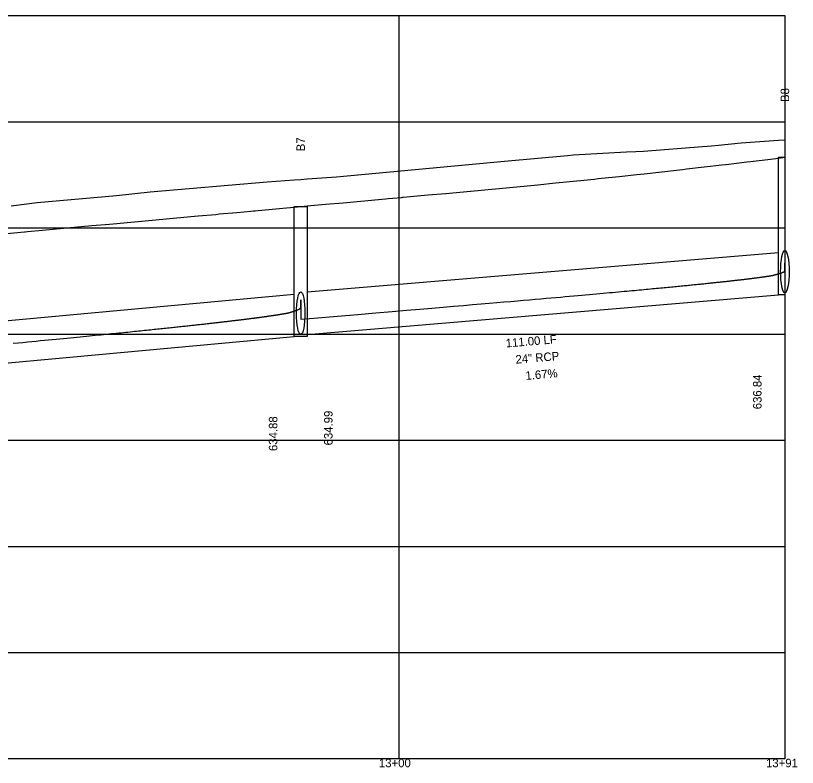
# Model space of a CAD drawing. Extents: x 2254979 to 2278074, y 13790855 to 13792793.
# Drawn here: x 2261170.4 to 2261354.4, y 13792139.4 to 13792316.4 of the extents above; entities that cross this region are included whole.
import ezdxf

# ---------------------------------------------------------------- set-up
doc = ezdxf.new("R2010")
doc.units = 0
for name, color, linetype in [('blank4', 7, 'Continuous'), ('D_DRN_PROF_HGL', 7, 'Continuous'), ('D_PROF_1', 7, 'Continuous'), ('D_PROF_NOTES_1', 7, 'Continuous'), ('Default', 7, 'Continuous'), ('Drain_PipeInside', 7, 'Continuous'), ('E_Terrain', 7, 'Continuous'), ('Inlet', 7, 'Continuous'), ('z - Construction', 7, 'Continuous')]:
    doc.layers.add(name, color=color, linetype=linetype)

msp = doc.modelspace()

# ---------------------------------------------------------------- linework, layer by layer
at = {"layer": 'blank4'}
msp.add_lwpolyline([(2259960.69, 13792141.44), (2259960.69, 13792316.44), (2261351.48, 13792316.44), (2261351.48, 13792141.44)], close=True, dxfattribs=at)
at = {"layer": 'D_DRN_PROF_HGL'}
msp.add_line((2261237.48, 13792249.54), (2261237.48, 13792244.93), dxfattribs=at)
for points in [[(2261237.48, 13792244.93), (2261240.56, 13792245.2), (2261246.13, 13792245.67), (2261250.95, 13792246.07), (2261255.19, 13792246.43), (2261258.99, 13792246.76), (2261262.41, 13792247.05), (2261265.53, 13792247.31), (2261268.39, 13792247.56), (2261271.04, 13792247.79), (2261273.49, 13792248), (2261275.78, 13792248.19), (2261277.92, 13792248.38), (2261279.94, 13792248.55), (2261281.84, 13792248.71), (2261283.63, 13792248.87), (2261285.34, 13792249.02), (2261286.95, 13792249.16), (2261288.49, 13792249.29), (2261289.96, 13792249.42), (2261291.37, 13792249.54), (2261292.72, 13792249.66), (2261294.01, 13792249.77), (2261295.24, 13792249.88), (2261296.43, 13792249.99), (2261297.58, 13792250.09), (2261298.69, 13792250.18), (2261299.75, 13792250.28), (2261300.78, 13792250.37), (2261301.77, 13792250.46), (2261302.74, 13792250.54), (2261303.67, 13792250.63), (2261304.57, 13792250.71), (2261305.45, 13792250.79), (2261306.29, 13792250.86), (2261307.12, 13792250.94), (2261307.92, 13792251.01), (2261308.7, 13792251.08), (2261309.46, 13792251.15), (2261310.19, 13792251.21), (2261310.91, 13792251.28), (2261311.61, 13792251.34), (2261312.29, 13792251.4), (2261312.96, 13792251.46), (2261313.6, 13792251.52), (2261314.24, 13792251.58), (2261314.85, 13792251.64), (2261315.46, 13792251.69), (2261316.05, 13792251.75), (2261316.62, 13792251.8), (2261317.19, 13792251.85), (2261317.74, 13792251.9), (2261318.28, 13792251.95), (2261318.8, 13792252), (2261319.32, 13792252.05), (2261319.82, 13792252.1), (2261320.32, 13792252.15), (2261320.8, 13792252.19), (2261321.28, 13792252.24), (2261321.74, 13792252.28), (2261322.2, 13792252.32), (2261322.65, 13792252.36), (2261323.09, 13792252.41), (2261323.52, 13792252.45), (2261323.94, 13792252.49), (2261324.35, 13792252.53), (2261324.76, 13792252.57), (2261325.16, 13792252.61), (2261325.55, 13792252.64), (2261325.94, 13792252.68), (2261326.32, 13792252.72), (2261326.69, 13792252.75), (2261327.05, 13792252.79), (2261327.41, 13792252.82), (2261327.77, 13792252.86), (2261328.11, 13792252.89), (2261328.45, 13792252.93), (2261328.79, 13792252.96), (2261329.12, 13792252.99), (2261329.44, 13792253.02), (2261329.76, 13792253.06), (2261330.08, 13792253.09), (2261330.39, 13792253.12), (2261330.69, 13792253.15), (2261330.99, 13792253.18), (2261331.28, 13792253.21), (2261331.57, 13792253.24), (2261331.86, 13792253.27), (2261332.14, 13792253.29), (2261332.42, 13792253.32), (2261332.69, 13792253.35), (2261332.96, 13792253.38), (2261333.22, 13792253.41), (2261333.48, 13792253.43), (2261333.74, 13792253.46), (2261333.99, 13792253.48), (2261334.24, 13792253.51), (2261334.49, 13792253.54), (2261334.73, 13792253.56), (2261334.97, 13792253.59), (2261335.2, 13792253.61), (2261335.43, 13792253.64), (2261335.66, 13792253.66), (2261335.89, 13792253.68), (2261336.11, 13792253.71), (2261336.33, 13792253.73), (2261336.54, 13792253.75), (2261336.76, 13792253.78), (2261336.97, 13792253.8), (2261337.17, 13792253.82), (2261337.38, 13792253.84), (2261337.58, 13792253.86), (2261337.78, 13792253.89), (2261337.97, 13792253.91), (2261338.16, 13792253.93), (2261338.36, 13792253.95), (2261338.54, 13792253.97), (2261338.73, 13792253.99), (2261338.91, 13792254.01), (2261339.09, 13792254.03), (2261339.27, 13792254.05), (2261339.45, 13792254.07), (2261339.62, 13792254.09), (2261339.79, 13792254.11), (2261339.96, 13792254.13), (2261340.13, 13792254.15), (2261340.29, 13792254.17), (2261340.45, 13792254.19), (2261340.61, 13792254.2), (2261340.77, 13792254.22), (2261340.93, 13792254.24), (2261341.08, 13792254.26), (2261341.23, 13792254.28), (2261341.38, 13792254.29), (2261341.53, 13792254.31), (2261341.68, 13792254.33), (2261341.82, 13792254.34), (2261341.97, 13792254.36), (2261342.11, 13792254.38), (2261342.25, 13792254.4), (2261342.38, 13792254.41), (2261342.52, 13792254.43), (2261342.65, 13792254.44), (2261342.79, 13792254.46), (2261342.92, 13792254.48), (2261343.04, 13792254.49), (2261343.17, 13792254.51), (2261343.3, 13792254.52), (2261343.42, 13792254.54), (2261343.54, 13792254.55), (2261343.67, 13792254.57), (2261343.78, 13792254.58), (2261343.9, 13792254.6), (2261344.02, 13792254.61), (2261344.13, 13792254.63), (2261344.25, 13792254.64), (2261344.36, 13792254.66), (2261344.47, 13792254.67), (2261344.58, 13792254.69), (2261344.69, 13792254.7), (2261344.8, 13792254.71), (2261344.9, 13792254.73), (2261345.01, 13792254.74), (2261345.11, 13792254.75), (2261345.21, 13792254.77), (2261345.31, 13792254.78), (2261345.41, 13792254.79), (2261345.51, 13792254.81), (2261345.6, 13792254.82), (2261345.7, 13792254.83), (2261345.79, 13792254.85), (2261345.89, 13792254.86), (2261345.98, 13792254.87), (2261346.07, 13792254.89), (2261346.16, 13792254.9), (2261346.25, 13792254.91), (2261346.33, 13792254.92), (2261346.42, 13792254.93), (2261346.51, 13792254.95), (2261346.59, 13792254.96), (2261346.67, 13792254.97), (2261346.75, 13792254.98), (2261346.84, 13792254.99), (2261346.92, 13792255.01), (2261346.99, 13792255.02), (2261347.07, 13792255.03), (2261347.15, 13792255.04), (2261347.23, 13792255.05), (2261347.3, 13792255.06), (2261347.37, 13792255.07), (2261347.45, 13792255.09), (2261347.52, 13792255.1), (2261347.59, 13792255.11), (2261347.66, 13792255.12), (2261347.73, 13792255.13), (2261347.8, 13792255.14), (2261347.87, 13792255.15), (2261347.93, 13792255.16), (2261348, 13792255.17), (2261348.06, 13792255.18), (2261348.13, 13792255.19), (2261348.19, 13792255.2), (2261348.25, 13792255.21), (2261348.32, 13792255.22), (2261348.38, 13792255.23), (2261348.44, 13792255.24), (2261348.5, 13792255.26), (2261348.55, 13792255.27), (2261348.61, 13792255.28), (2261348.67, 13792255.3), (2261348.73, 13792255.31), (2261348.78, 13792255.33), (2261348.84, 13792255.34), (2261348.89, 13792255.36), (2261348.94, 13792255.37), (2261348.99, 13792255.38), (2261349.05, 13792255.4), (2261349.1, 13792255.41), (2261349.15, 13792255.42), (2261349.2, 13792255.44), (2261349.25, 13792255.45), (2261349.29, 13792255.46), (2261349.34, 13792255.48), (2261349.39, 13792255.49), (2261349.43, 13792255.5), (2261349.48, 13792255.51), (2261349.53, 13792255.53), (2261349.57, 13792255.54), (2261349.61, 13792255.55), (2261349.66, 13792255.56), (2261349.7, 13792255.58), (2261349.74, 13792255.59), (2261349.78, 13792255.6), (2261349.82, 13792255.61), (2261349.86, 13792255.62), (2261349.9, 13792255.63), (2261349.94, 13792255.65), (2261349.98, 13792255.66), (2261350.01, 13792255.67), (2261350.05, 13792255.68), (2261350.09, 13792255.69), (2261350.12, 13792255.7), (2261350.16, 13792255.71), (2261350.19, 13792255.72), (2261350.23, 13792255.73), (2261350.26, 13792255.75), (2261350.29, 13792255.76), (2261350.32, 13792255.77), (2261350.36, 13792255.78), (2261350.39, 13792255.79), (2261350.42, 13792255.8), (2261350.45, 13792255.81), (2261350.48, 13792255.82), (2261350.51, 13792255.83), (2261350.54, 13792255.84), (2261350.56, 13792255.85), (2261350.59, 13792255.86), (2261350.62, 13792255.87), (2261350.64, 13792255.87), (2261350.67, 13792255.88), (2261350.7, 13792255.89), (2261350.72, 13792255.9), (2261350.75, 13792255.91), (2261350.77, 13792255.92), (2261350.79, 13792255.93), (2261350.82, 13792255.94), (2261350.84, 13792255.95), (2261350.86, 13792255.96), (2261350.88, 13792255.96), (2261350.91, 13792255.97), (2261350.93, 13792255.98), (2261350.95, 13792255.99), (2261350.97, 13792256), (2261350.99, 13792256.01), (2261351.01, 13792256.02), (2261351.02, 13792256.02), (2261351.04, 13792256.03), (2261351.06, 13792256.04), (2261351.08, 13792256.05), (2261351.1, 13792256.06), (2261351.11, 13792256.06), (2261351.13, 13792256.07), (2261351.14, 13792256.08), (2261351.16, 13792256.09), (2261351.17, 13792256.09), (2261351.19, 13792256.1), (2261351.2, 13792256.11), (2261351.22, 13792256.12), (2261351.23, 13792256.12), (2261351.24, 13792256.13), (2261351.26, 13792256.14), (2261351.27, 13792256.14), (2261351.28, 13792256.15), (2261351.29, 13792256.16), (2261351.3, 13792256.16), (2261351.31, 13792256.17), (2261351.32, 13792256.18), (2261351.33, 13792256.19), (2261351.34, 13792256.19), (2261351.35, 13792256.2), (2261351.36, 13792256.2), (2261351.37, 13792256.21), (2261351.38, 13792256.22), (2261351.39, 13792256.22), (2261351.39, 13792256.23), (2261351.4, 13792256.24), (2261351.41, 13792256.24), (2261351.41, 13792256.25), (2261351.42, 13792256.25), (2261351.43, 13792256.26), (2261351.43, 13792256.27), (2261351.44, 13792256.27), (2261351.44, 13792256.28), (2261351.45, 13792256.28), (2261351.45, 13792256.29), (2261351.45, 13792256.3), (2261351.46, 13792256.3), (2261351.46, 13792256.31), (2261351.46, 13792256.31), (2261351.47, 13792256.32), (2261351.47, 13792256.32), (2261351.47, 13792256.33), (2261351.47, 13792256.33), (2261351.47, 13792256.34), (2261351.48, 13792256.34), (2261351.48, 13792256.35), (2261351.48, 13792256.35), (2261351.48, 13792256.36), (2261351.48, 13792258.2)], [(2261169.78, 13792239.29), (2261170.93, 13792239.4), (2261172.04, 13792239.5), (2261173.12, 13792239.61), (2261174.16, 13792239.71), (2261175.18, 13792239.81), (2261176.17, 13792239.9), (2261177.14, 13792240), (2261178.08, 13792240.09), (2261178.99, 13792240.18), (2261179.88, 13792240.26), (2261180.75, 13792240.35), (2261181.6, 13792240.43), (2261182.43, 13792240.51), (2261183.24, 13792240.59), (2261184.03, 13792240.67), (2261184.8, 13792240.75), (2261185.56, 13792240.82), (2261186.29, 13792240.89), (2261187.02, 13792240.96), (2261187.72, 13792241.03), (2261188.42, 13792241.1), (2261189.09, 13792241.17), (2261189.76, 13792241.24), (2261190.41, 13792241.3), (2261191.05, 13792241.36), (2261191.67, 13792241.43), (2261192.29, 13792241.49), (2261192.89, 13792241.55), (2261193.48, 13792241.61), (2261194.06, 13792241.67), (2261194.63, 13792241.72), (2261195.19, 13792241.78), (2261195.74, 13792241.84), (2261196.28, 13792241.89), (2261196.81, 13792241.94), (2261197.33, 13792242), (2261197.84, 13792242.05), (2261198.34, 13792242.1), (2261198.83, 13792242.15), (2261199.32, 13792242.2), (2261199.8, 13792242.25), (2261200.27, 13792242.3), (2261200.73, 13792242.34), (2261201.19, 13792242.39), (2261201.63, 13792242.44), (2261202.08, 13792242.48), (2261202.51, 13792242.53), (2261202.94, 13792242.57), (2261203.36, 13792242.62), (2261203.77, 13792242.66), (2261204.18, 13792242.7), (2261204.58, 13792242.74), (2261204.98, 13792242.78), (2261205.37, 13792242.83), (2261205.76, 13792242.87), (2261206.13, 13792242.91), (2261206.51, 13792242.95), (2261206.88, 13792242.98), (2261207.24, 13792243.02), (2261207.6, 13792243.06), (2261207.95, 13792243.1), (2261208.3, 13792243.14), (2261208.64, 13792243.17), (2261208.98, 13792243.21), (2261209.32, 13792243.24), (2261209.65, 13792243.28), (2261209.97, 13792243.31), (2261210.29, 13792243.35), (2261210.61, 13792243.38), (2261210.92, 13792243.42), (2261211.23, 13792243.45), (2261211.53, 13792243.48), (2261211.84, 13792243.52), (2261212.13, 13792243.55), (2261212.43, 13792243.58), (2261212.71, 13792243.61), (2261213, 13792243.64), (2261213.28, 13792243.67), (2261213.56, 13792243.7), (2261213.84, 13792243.73), (2261214.11, 13792243.76), (2261214.38, 13792243.79), (2261214.64, 13792243.82), (2261214.9, 13792243.85), (2261215.16, 13792243.88), (2261215.42, 13792243.91), (2261215.67, 13792243.94), (2261215.92, 13792243.97), (2261216.17, 13792243.99), (2261216.41, 13792244.02), (2261216.65, 13792244.05), (2261216.89, 13792244.07), (2261217.12, 13792244.1), (2261217.36, 13792244.13), (2261217.58, 13792244.15), (2261217.81, 13792244.18), (2261218.04, 13792244.2), (2261218.26, 13792244.23), (2261218.48, 13792244.26), (2261218.69, 13792244.28), (2261218.91, 13792244.31), (2261219.12, 13792244.33), (2261219.33, 13792244.35), (2261219.54, 13792244.38), (2261219.74, 13792244.4), (2261219.95, 13792244.43), (2261220.15, 13792244.45), (2261220.34, 13792244.47), (2261220.54, 13792244.49), (2261220.73, 13792244.52), (2261220.93, 13792244.54), (2261221.12, 13792244.56), (2261221.3, 13792244.59), (2261221.49, 13792244.61), (2261221.67, 13792244.63), (2261221.85, 13792244.65), (2261222.03, 13792244.67), (2261222.21, 13792244.69), (2261222.39, 13792244.71), (2261222.56, 13792244.74), (2261222.73, 13792244.76), (2261222.9, 13792244.78), (2261223.07, 13792244.8), (2261223.24, 13792244.82), (2261223.4, 13792244.84), (2261223.57, 13792244.86), (2261223.73, 13792244.88), (2261223.89, 13792244.9), (2261224.05, 13792244.92), (2261224.2, 13792244.94), (2261224.36, 13792244.96), (2261224.51, 13792244.97), (2261224.66, 13792244.99), (2261224.81, 13792245.01), (2261224.96, 13792245.03), (2261225.11, 13792245.05), (2261225.25, 13792245.07), (2261225.4, 13792245.09), (2261225.54, 13792245.1), (2261225.68, 13792245.12), (2261225.82, 13792245.14), (2261225.96, 13792245.16), (2261226.09, 13792245.18), (2261226.23, 13792245.19), (2261226.36, 13792245.21), (2261226.5, 13792245.23), (2261226.63, 13792245.24), (2261226.76, 13792245.26), (2261226.89, 13792245.28), (2261227.01, 13792245.29), (2261227.14, 13792245.31), (2261227.26, 13792245.33), (2261227.39, 13792245.34), (2261227.51, 13792245.36), (2261227.63, 13792245.38), (2261227.75, 13792245.39), (2261227.87, 13792245.41), (2261227.99, 13792245.42), (2261228.1, 13792245.44), (2261228.22, 13792245.46), (2261228.33, 13792245.47), (2261228.45, 13792245.49), (2261228.56, 13792245.5), (2261228.67, 13792245.52), (2261228.78, 13792245.53), (2261228.89, 13792245.55), (2261228.99, 13792245.56), (2261229.1, 13792245.58), (2261229.2, 13792245.59), (2261229.31, 13792245.61), (2261229.41, 13792245.62), (2261229.51, 13792245.63), (2261229.61, 13792245.65), (2261229.71, 13792245.66), (2261229.81, 13792245.68), (2261229.91, 13792245.69), (2261230.01, 13792245.71), (2261230.1, 13792245.72), (2261230.2, 13792245.73), (2261230.29, 13792245.75), (2261230.39, 13792245.76), (2261230.48, 13792245.77), (2261230.57, 13792245.79), (2261230.66, 13792245.8), (2261230.75, 13792245.81), (2261230.84, 13792245.83), (2261230.93, 13792245.84), (2261231.01, 13792245.85), (2261231.1, 13792245.87), (2261231.18, 13792245.88), (2261231.27, 13792245.89), (2261231.35, 13792245.9), (2261231.43, 13792245.92), (2261231.52, 13792245.93), (2261231.6, 13792245.94), (2261231.68, 13792245.95), (2261231.76, 13792245.97), (2261231.84, 13792245.98), (2261231.91, 13792245.99), (2261231.99, 13792246), (2261232.07, 13792246.01), (2261232.14, 13792246.03), (2261232.22, 13792246.04), (2261232.29, 13792246.05), (2261232.36, 13792246.06), (2261232.44, 13792246.07), (2261232.51, 13792246.08), (2261232.58, 13792246.1), (2261232.65, 13792246.11), (2261232.72, 13792246.12), (2261232.79, 13792246.13), (2261232.85, 13792246.14), (2261232.92, 13792246.15), (2261232.99, 13792246.16), (2261233.05, 13792246.18), (2261233.12, 13792246.19), (2261233.18, 13792246.2), (2261233.25, 13792246.21), (2261233.31, 13792246.22), (2261233.37, 13792246.23), (2261233.44, 13792246.24), (2261233.5, 13792246.25), (2261233.56, 13792246.26), (2261233.62, 13792246.27), (2261233.68, 13792246.28), (2261233.74, 13792246.29), (2261233.79, 13792246.3), (2261233.85, 13792246.31), (2261233.91, 13792246.32), (2261233.96, 13792246.33), (2261234.02, 13792246.34), (2261234.07, 13792246.35), (2261234.13, 13792246.36), (2261234.18, 13792246.37), (2261234.24, 13792246.38), (2261234.29, 13792246.39), (2261234.34, 13792246.4), (2261234.39, 13792246.41), (2261234.44, 13792246.42), (2261234.49, 13792246.43), (2261234.54, 13792246.45), (2261234.59, 13792246.46), (2261234.64, 13792246.48), (2261234.69, 13792246.49), (2261234.74, 13792246.5), (2261234.78, 13792246.52), (2261234.83, 13792246.53), (2261234.88, 13792246.54), (2261234.92, 13792246.56), (2261234.97, 13792246.57), (2261235.01, 13792246.58), (2261235.06, 13792246.6), (2261235.1, 13792246.61), (2261235.14, 13792246.62), (2261235.18, 13792246.64), (2261235.23, 13792246.65), (2261235.27, 13792246.66), (2261235.31, 13792246.67), (2261235.35, 13792246.69), (2261235.39, 13792246.7), (2261235.43, 13792246.71), (2261235.47, 13792246.72), (2261235.51, 13792246.74), (2261235.54, 13792246.75), (2261235.58, 13792246.76), (2261235.62, 13792246.77), (2261235.66, 13792246.78), (2261235.69, 13792246.79), (2261235.73, 13792246.81), (2261235.76, 13792246.82), (2261235.8, 13792246.83), (2261235.83, 13792246.84), (2261235.87, 13792246.85), (2261235.9, 13792246.86), (2261235.93, 13792246.87), (2261235.97, 13792246.88), (2261236, 13792246.9), (2261236.03, 13792246.91), (2261236.06, 13792246.92), (2261236.09, 13792246.93), (2261236.12, 13792246.94), (2261236.15, 13792246.95), (2261236.18, 13792246.96), (2261236.21, 13792246.97), (2261236.24, 13792246.98), (2261236.27, 13792246.99), (2261236.3, 13792247), (2261236.33, 13792247.01), (2261236.35, 13792247.02), (2261236.38, 13792247.03), (2261236.41, 13792247.04), (2261236.43, 13792247.05), (2261236.46, 13792247.06), (2261236.48, 13792247.07), (2261236.51, 13792247.08), (2261236.53, 13792247.09), (2261236.56, 13792247.1), (2261236.58, 13792247.11), (2261236.61, 13792247.12), (2261236.63, 13792247.13), (2261236.65, 13792247.14), (2261236.67, 13792247.14), (2261236.7, 13792247.15), (2261236.72, 13792247.16), (2261236.74, 13792247.17), (2261236.76, 13792247.18), (2261236.78, 13792247.19), (2261236.8, 13792247.2), (2261236.82, 13792247.21), (2261236.84, 13792247.22), (2261236.86, 13792247.22), (2261236.88, 13792247.23), (2261236.9, 13792247.24), (2261236.92, 13792247.25), (2261236.93, 13792247.26), (2261236.95, 13792247.27), (2261236.97, 13792247.27), (2261236.99, 13792247.28), (2261237, 13792247.29), (2261237.02, 13792247.3), (2261237.04, 13792247.31), (2261237.05, 13792247.31), (2261237.07, 13792247.32), (2261237.08, 13792247.33), (2261237.1, 13792247.34), (2261237.11, 13792247.34), (2261237.12, 13792247.35), (2261237.14, 13792247.36), (2261237.15, 13792247.37), (2261237.17, 13792247.37), (2261237.18, 13792247.38), (2261237.19, 13792247.39), (2261237.2, 13792247.4), (2261237.22, 13792247.4), (2261237.23, 13792247.41), (2261237.24, 13792247.42), (2261237.25, 13792247.43), (2261237.26, 13792247.43), (2261237.27, 13792247.44), (2261237.28, 13792247.45), (2261237.29, 13792247.45), (2261237.3, 13792247.46), (2261237.31, 13792247.47), (2261237.32, 13792247.47), (2261237.33, 13792247.48), (2261237.34, 13792247.49), (2261237.35, 13792247.49), (2261237.35, 13792247.5), (2261237.36, 13792247.51), (2261237.37, 13792247.51), (2261237.38, 13792247.52), (2261237.38, 13792247.52), (2261237.39, 13792247.53), (2261237.4, 13792247.54), (2261237.4, 13792247.54), (2261237.41, 13792247.55), (2261237.41, 13792247.56), (2261237.42, 13792247.56), (2261237.42, 13792247.57), (2261237.43, 13792247.57), (2261237.43, 13792247.58), (2261237.44, 13792247.59), (2261237.44, 13792247.59), (2261237.45, 13792247.6), (2261237.45, 13792247.6), (2261237.45, 13792247.61), (2261237.46, 13792247.61), (2261237.46, 13792247.62), (2261237.46, 13792247.62), (2261237.47, 13792247.63), (2261237.47, 13792247.64), (2261237.47, 13792247.64), (2261237.47, 13792247.65), (2261237.47, 13792247.65), (2261237.47, 13792247.66), (2261237.47, 13792247.66), (2261237.48, 13792247.67), (2261237.48, 13792247.67), (2261237.48, 13792247.68), (2261237.48, 13792247.68), (2261237.48, 13792249.54)]]:
    msp.add_lwpolyline(points, dxfattribs=at)
at = {"layer": 'D_PROF_1'}
msp.add_lwpolyline([(2261167.48, 13792265.08), (2261171.61, 13792265.46), (2261172.48, 13792265.54), (2261172.49, 13792265.54), (2261172.53, 13792265.54), (2261172.64, 13792265.55), (2261173.14, 13792265.6), (2261176.72, 13792265.93), (2261177.48, 13792265.99), (2261178.34, 13792266.07), (2261182.48, 13792266.45), (2261186.61, 13792266.83), (2261187.48, 13792266.91), (2261188.34, 13792266.99), (2261192.48, 13792267.37), (2261193.33, 13792267.44), (2261197.48, 13792267.82), (2261198.33, 13792267.9), (2261202.48, 13792268.28), (2261206.63, 13792268.66), (2261207.48, 13792268.74), (2261208.33, 13792268.81), (2261212.48, 13792269.19), (2261213.32, 13792269.27), (2261217.48, 13792269.65), (2261218.32, 13792269.73), (2261222.48, 13792270.11), (2261225.73, 13792270.41), (2261226.38, 13792270.47), (2261226.42, 13792270.47), (2261226.59, 13792270.48), (2261226.74, 13792270.5), (2261227.48, 13792270.57), (2261231.64, 13792270.95), (2261232.48, 13792271.02), (2261233.31, 13792271.1), (2261235.98, 13792271.34), (2261235.98, 13792271.34), (2261237.48, 13792271.48), (2261237.48, 13792271.48), (2261238.31, 13792271.55), (2261238.98, 13792271.62), (2261238.98, 13792271.62), (2261242.48, 13792271.93), (2261243.31, 13792272.01), (2261247.48, 13792272.39), (2261251.64, 13792272.77), (2261252.48, 13792272.84), (2261253.31, 13792272.92), (2261257.48, 13792273.3), (2261258.11, 13792273.36), (2261261.27, 13792273.64), (2261261.31, 13792273.65), (2261261.47, 13792273.66), (2261261.64, 13792273.68), (2261262.48, 13792273.75), (2261266.64, 13792274.13), (2261267.48, 13792274.21), (2261271.64, 13792274.59), (2261272.48, 13792274.66), (2261273.31, 13792274.74), (2261277.48, 13792275.12), (2261277.49, 13792275.12), (2261277.54, 13792275.12), (2261281.65, 13792275.5), (2261282.48, 13792275.58), (2261283.31, 13792275.66), (2261287.48, 13792276.05), (2261291.64, 13792276.45), (2261292.48, 13792276.53), (2261293.31, 13792276.62), (2261297.48, 13792277.03), (2261298.31, 13792277.11), (2261302.48, 13792277.53), (2261306.64, 13792277.97), (2261307.48, 13792278.05), (2261308.31, 13792278.14), (2261312.48, 13792278.58), (2261316.64, 13792279.03), (2261317.48, 13792279.12), (2261318.31, 13792279.21), (2261322.48, 13792279.67), (2261326.64, 13792280.14), (2261327.48, 13792280.23), (2261328.31, 13792280.33), (2261332.48, 13792280.81), (2261336.64, 13792281.3), (2261337.48, 13792281.39), (2261338.31, 13792281.49), (2261342.48, 13792281.99), (2261342.53, 13792282), (2261342.54, 13792282), (2261343.36, 13792282.1), (2261347.48, 13792282.6), (2261349.98, 13792282.91), (2261349.98, 13792282.91), (2261351.48, 13792283.09)], dxfattribs=at)
at = {"layer": 'Default'}
msp.add_line((2261260.69, 13792141.44), (2261260.69, 13792316.44), dxfattribs=at)
at = {"layer": 'Drain_PipeInside'}
for p, q in [((2261238.98, 13792251.37), (2261349.98, 13792260.66)), ((2260989.08, 13792228.18), (2261235.98, 13792250.87)), ((2261238.98, 13792241.37), (2261349.98, 13792250.66)), ((2260989.08, 13792218.18), (2261235.98, 13792240.87))]:
    msp.add_line(p, q, dxfattribs=at)
for centre in [(2261351.48, 13792256.16), (2261351.48, 13792256.15), (2261237.48, 13792246.37), (2261237.48, 13792246.37)]:
    msp.add_ellipse(centre, major_axis=(0, 5), ratio=0.2, dxfattribs=at)
at = {"layer": 'E_Terrain'}
msp.add_lwpolyline([(2261169.35, 13792271.67), (2261175.42, 13792272.4), (2261194.11, 13792274.05), (2261202.07, 13792274.92), (2261229.62, 13792277.32), (2261235.98, 13792277.77), (2261235.98, 13792277.77), (2261237.48, 13792277.88), (2261237.48, 13792277.88), (2261238.98, 13792277.99), (2261238.98, 13792277.99), (2261245.94, 13792278.49), (2261285.44, 13792282.14), (2261300.32, 13792283.54), (2261301.64, 13792283.69), (2261314.18, 13792284.33), (2261316.38, 13792284.48), (2261318.18, 13792284.54), (2261332.09, 13792285.64), (2261333.17, 13792285.71), (2261334.2, 13792285.82), (2261335.86, 13792285.97), (2261341.21, 13792286.52), (2261349.98, 13792287.1), (2261349.98, 13792287.1), (2261351.48, 13792287.2)], dxfattribs=at)
at = {"layer": 'Inlet'}
for points in [[(2261349.98, 13792283.09), (2261351.48, 13792283.09), (2261351.48, 13792250.66), (2261349.98, 13792250.66)], [(2261235.98, 13792271.48), (2261238.98, 13792271.48), (2261238.98, 13792240.87), (2261235.98, 13792240.87)]]:
    msp.add_lwpolyline(points, close=True, dxfattribs=at)
at = {"layer": 'z - Construction'}
for p, q in [((2259960.69, 13792291.44), (2261351.48, 13792291.44)), ((2259960.69, 13792266.44), (2261351.48, 13792266.44)), ((2259960.69, 13792241.44), (2261351.48, 13792241.44)), ((2259960.69, 13792216.44), (2261351.48, 13792216.44)), ((2259960.69, 13792191.44), (2261351.48, 13792191.44)), ((2259960.69, 13792166.44), (2261351.48, 13792166.44))]:
    msp.add_line(p, q, dxfattribs=at)

# ---------------------------------------------------------------- texts
at = {"layer": 'D_PROF_NOTES_1'}
for s, rotation, p in [('B8', 90, (2261352.48, 13792296.1)), ('B7', 90, (2261238.48, 13792284.5)), ('111.00 LF', 4.7841, (2261285.83, 13792238.29)), ('24" RCP', 4.7841, (2261288.15, 13792234.47)), ('1.67%', 4.7841, (2261290.48, 13792230.65)), ('636.84', 90, (2261345.98, 13792223.75)), ('634.99', 90, (2261244.98, 13792215.23)), ('634.88', 90, (2261231.98, 13792213.9))]:
    msp.add_text(s, height=2, rotation=rotation, dxfattribs=at).set_placement(p)
at = {"layer": 'Default'}
for s, p in [('13+00', (2261255.89, 13792139.44)), ('13+91', (2261347.03, 13792139.44))]:
    msp.add_text(s, height=2, dxfattribs=at).set_placement(p)

doc.saveas('drawing.dxf')
